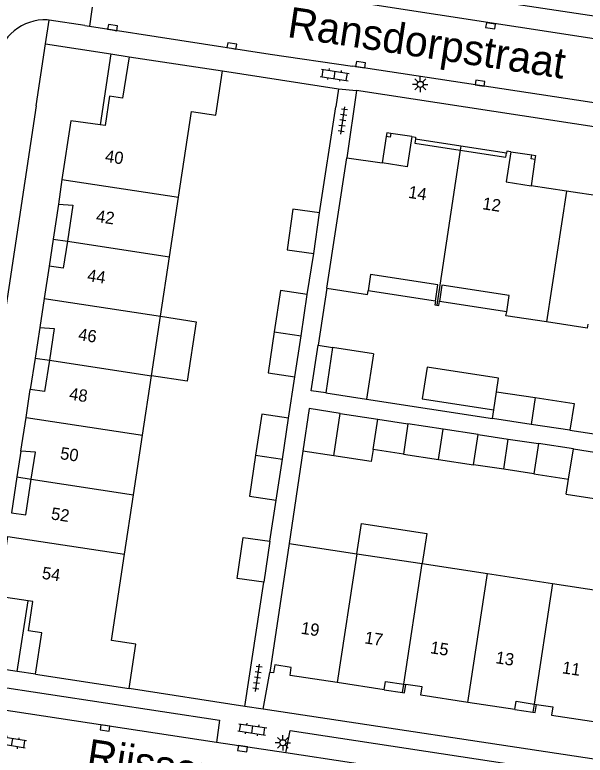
# Model space of a CAD drawing. Extents: x 124000 to 128010, y 398999 to 403000.
# Drawn here: x 126578 to 126624.6, y 399996.7 to 400057.2 of the extents above; entities that cross this region are included whole.
import ezdxf

# ---------------------------------------------------------------- set-up
doc = ezdxf.new("R2010")
doc.units = 0
for name, color, linetype in [('gg-afsc-erfafscheiding', 7, 'Continuous'), ('gg-afsc-hekwerk', 7, 'Continuous'), ('gg-afsc-muur', 7, 'Continuous'), ('gg-anno-huisnummerreeks BGT', 7, 'Continuous'), ('gg-anno-openbare ruimte label', 7, 'Continuous'), ('gg-bbg-bijgebouw', 7, 'Continuous'), ('gg-bbg-gedigitaliseerde bijgebouw', 7, 'Continuous'), ('gg-bbg-hoofdgebouw', 7, 'Continuous'), ('gg-bbg-luifel en loopbrug', 7, 'Continuous'), ('gg-bbg-onder overbouw', 7, 'Continuous'), ('gg-bbg-pand overbouw', 7, 'Continuous'), ('gg-bbg-pilaar onder overbouw', 7, 'Continuous'), ('gg-bbg-pilaar pand', 7, 'Continuous'), ('gg-bbg-tussenscheiding', 7, 'Continuous'), ('gg-bbg-tussenscheiding niveau 01', 7, 'Continuous'), ('gg-knt-verharding', 7, 'Continuous'), ('gg-knt-verharding nz', 7, 'Continuous'), ('gt-grn-weggrens', 7, 'Continuous'), ('gt-symb-klinker verharding', 7, 'Continuous'), ('gt-symb-kolk', 7, 'Continuous'), ('gt-symb-lichtmast', 7, 'Continuous'), ('gt-symb-tegel verharding', 7, 'Continuous')]:
    doc.layers.add(name, color=color, linetype=linetype)

# ---------------------------------------------------------------- blocks, each defined once
blk = doc.blocks.new('gt0-KOLK')
at = {"layer": 'gt-symb-kolk'}
blk.add_lwpolyline([(0, 0), (0.375, 0), (0.375, 0.4), (-0.375, 0.4), (-0.375, 0), (0, 0)], dxfattribs=at)
blk = doc.blocks.new('gt0-TEG1')
at = {"layer": 'gt-symb-tegel verharding'}
for p, q in [((-1.125, 0), (1.125, 0)), ((-0.9, -0.25), (-0.9, 0.25)), ((-0.45, -0.25), (-0.45, 0.25)), ((0, -0.25), (0, 0.25)), ((0.45, -0.25), (0.45, 0.25)), ((0.9, -0.25), (0.9, 0.25))]:
    blk.add_line(p, q, dxfattribs=at)
blk = doc.blocks.new('gt0-LMAST')
at = {"layer": 'gt-symb-lichtmast'}
for p, q in [((-0.005, 0.246), (-0.005, 0.621)), ((-0.182, 0.173), (-0.447, 0.438)), ((0.172, 0.173), (0.437, 0.438)), ((-0.255, -0.004), (-0.63, -0.004)), ((-0.182, -0.181), (-0.447, -0.446)), ((-0.005, -0.254), (-0.005, -0.629)), ((0.437, -0.446), (0.172, -0.181)), ((0.245, -0.004), (0.62, -0.004))]:
    blk.add_line(p, q, dxfattribs=at)
blk.add_circle((-0.005, -0.004), 0.25, dxfattribs=at)
blk = doc.blocks.new('gt0-KL1')
at = {"layer": 'gt-symb-klinker verharding'}
for p, q in [((-1.15, 0.3), (1.15, 0.3)), ((-1, -0.3), (-1, 0.3)), ((-0.5, 0.3), (-0.5, 0.45)), ((0, -0.3), (0, 0.3)), ((0.5, 0.3), (0.5, 0.45)), ((1, -0.3), (1, 0.3)), ((-1.15, -0.3), (1.15, -0.3)), ((-0.5, -0.45), (-0.5, -0.3)), ((0.5, -0.45), (0.5, -0.3))]:
    blk.add_line(p, q, dxfattribs=at)

msp = doc.modelspace()

# ---------------------------------------------------------------- linework, layer by layer
at = {"layer": 'gg-afsc-erfafscheiding'}
for p, q in [((126602.909, 400040.99), (126604.252, 400049.649)), ((126601.919, 400034.294), (126602.455, 400037.649)), ((126603.515, 400034.814), (126602.807, 400030.165)), ((126600.386, 400024.195), (126600.903, 400027.573)), ((126606.759, 400025.761), (126617.047, 400024.183)), ((126623.379, 400023.217), (126629.177, 400022.318)), ((126601.559, 400021.521), (126600.44, 400013.969)), ((126598.846, 400014.149), (126599.382, 400017.5))]:
    msp.add_line(p, q, dxfattribs=at)
at = {"layer": 'gg-afsc-hekwerk'}
msp.add_line((126596.82, 400000.66), (126598.377, 400010.794), dxfattribs=at)
at = {"layer": 'gg-afsc-muur'}
for p, q in [((126594.982, 400052.569), (126604.47, 400051.111)), ((126604.47, 400051.111), (126604.252, 400049.649)), ((126596.82, 400000.66), (126587.348, 400002.126))]:
    msp.add_line(p, q, dxfattribs=at)
at = {"layer": 'gg-bbg-bijgebouw'}
for p, q in [((126602.455, 400037.649), (126602.909, 400040.99)), ((126601.411, 400030.934), (126601.919, 400034.294)), ((126600.903, 400027.573), (126601.411, 400030.934)), ((126602.807, 400030.165), (126603.987, 400029.985)), ((126603.987, 400029.985), (126603.421, 400026.27)), ((126617.154, 400024.881), (126617.381, 400026.366)), ((126617.381, 400026.366), (126620.544, 400025.883)), ((126617.047, 400024.183), (126617.154, 400024.881)), ((126599.884, 400020.847), (126600.386, 400024.195)), ((126620.215, 400023.7), (126617.047, 400024.183)), ((126623.379, 400023.217), (126620.215, 400023.7)), ((126599.382, 400017.5), (126599.884, 400020.847)), ((126598.846, 400014.149), (126598.377, 400010.794))]:
    msp.add_line(p, q, dxfattribs=at)
for points in [[(126602.909, 400040.99), (126600.737, 400041.285), (126600.283, 400037.944), (126602.455, 400037.649)], [(126601.919, 400034.294), (126599.73, 400034.625), (126599.222, 400031.265)], [(126599.222, 400031.265), (126598.714, 400027.904), (126600.903, 400027.573)], [(126603.421, 400026.27), (126602.241, 400026.45), (126602.807, 400030.165)], [(126620.544, 400025.883), (126623.712, 400025.399), (126623.379, 400023.217)], [(126600.386, 400024.195), (126598.195, 400024.524), (126597.693, 400021.176)], [(126597.693, 400021.176), (126597.191, 400017.828), (126599.382, 400017.5)], [(126598.377, 400010.794), (126596.195, 400011.099), (126596.664, 400014.454), (126598.846, 400014.149)]]:
    msp.add_lwpolyline(points, dxfattribs=at)
at = {"layer": 'gg-bbg-gedigitaliseerde bijgebouw'}
for p, q in [((126604.087, 400021.137), (126604.612, 400024.588)), ((126604.612, 400024.588), (126607.669, 400024.122)), ((126607.669, 400024.122), (126610.142, 400023.746)), ((126610.142, 400023.746), (126609.766, 400021.276)), ((126615.499, 400020.404), (126615.874, 400022.875)), ((126615.874, 400022.875), (126618.344, 400022.5)), ((126618.344, 400022.5), (126620.816, 400022.124)), ((126609.766, 400021.276), (126607.297, 400021.651)), ((126620.816, 400022.124), (126620.44, 400019.653)), ((126623.269, 400019.223), (126623.661, 400021.691)), ((126623.661, 400021.691), (126629.076, 400020.868)), ((126617.971, 400020.028), (126615.499, 400020.404)), ((126620.44, 400019.653), (126617.971, 400020.028)), ((126623.073, 400017.986), (126623.269, 400019.223)), ((126623.073, 400017.986), (126628.488, 400017.165))]:
    msp.add_line(p, q, dxfattribs=at)
msp.add_lwpolyline([(126607.297, 400021.651), (126607.148, 400020.671), (126604.087, 400021.137)], dxfattribs=at)
at = {"layer": 'gg-bbg-hoofdgebouw'}
for p, q in [((126587.346, 400053.732), (126594.982, 400052.569)), ((126603.515, 400034.814), (126605.137, 400045.482)), ((126605.137, 400045.482), (126608.042, 400045.061)), ((126581.869, 400043.696), (126581.571, 400041.693)), ((126623.101, 400042.751), (126620.204, 400043.191)), ((126626.002, 400042.311), (126623.101, 400042.751)), ((126590.662, 400037.39), (126591.397, 400042.25)), ((126589.927, 400032.531), (126590.662, 400037.39)), ((126580.809, 400036.632), (126580.405, 400033.976)), ((126580.405, 400033.976), (126580.045, 400031.607)), ((126589.191, 400027.672), (126589.927, 400032.531)), ((126588.456, 400022.812), (126589.191, 400027.672)), ((126578.929, 400024.258), (126579.277, 400026.546)), ((126578.512, 400021.517), (126578.929, 400024.258)), ((126587.72, 400017.953), (126588.456, 400022.812)), ((126586.985, 400013.094), (126587.72, 400017.953)), ((126600.44, 400013.969), (126598.842, 400003.44)), ((126600.44, 400013.969), (126605.962, 400013.131)), ((126605.962, 400013.131), (126611.299, 400012.321)), ((126611.299, 400012.321), (126616.649, 400011.509)), ((126616.649, 400011.509), (126621.968, 400010.702)), ((126621.968, 400010.702), (126627.307, 400009.892)), ((126579.691, 400003.284), (126587.348, 400002.126)), ((126608.197, 400002.024), (126604.354, 400002.604)), ((126618.886, 400000.401), (126615.042, 400000.987))]:
    msp.add_line(p, q, dxfattribs=at)
for points in [[(126587.346, 400053.732), (126586.827, 400050.352), (126585.755, 400050.501), (126585.392, 400048.113), (126584.982, 400048.17)], [(126591.397, 400042.25), (126592.457, 400049.251), (126594.434, 400048.949), (126594.982, 400052.569)], [(126584.982, 400048.17), (126582.586, 400048.505), (126581.869, 400043.696)], [(126610.459, 400047.203), (126610.767, 400047.161), (126610.747, 400047.009)], [(126618.545, 400045.97), (126618.218, 400046.019), (126618.198, 400045.862)], [(126603.515, 400034.814), (126606.843, 400034.306), (126606.892, 400034.615)], [(126612.381, 400033.764), (126612.332, 400033.459), (126612.49, 400033.435)], [(126612.49, 400033.435), (126612.657, 400033.41), (126612.708, 400033.742)], [(126621.476, 400032.068), (126618.154, 400032.572), (126618.224, 400032.888)], [(126624.844, 400031.886), (126624.795, 400031.564), (126621.476, 400032.068)], [(126579.092, 400009.291), (126576.702, 400009.644), (126577.453, 400014.541)], [(126587.348, 400002.126), (126587.896, 400005.744), (126585.918, 400006.043), (126586.985, 400013.094)], [(126579.691, 400003.284), (126580.209, 400006.672), (126579.121, 400006.837), (126579.492, 400009.232), (126579.092, 400009.291)], [(126604.354, 400002.604), (126600.507, 400003.185), (126600.607, 400003.847), (126599.256, 400004.059), (126599.142, 400003.389), (126598.842, 400003.44)], [(126615.042, 400000.987), (126611.193, 400001.574), (126611.297, 400002.256), (126609.974, 400002.45)], [(126620.645, 400000.825), (126621.977, 400000.625), (126621.874, 399999.953), (126625.699, 399999.366)]]:
    msp.add_lwpolyline(points, dxfattribs=at)
at = {"layer": 'gg-bbg-luifel en loopbrug'}
for p, q in [((126585.864, 400053.962), (126584.982, 400048.17)), ((126585.864, 400053.962), (126587.346, 400053.732)), ((126607.328, 400029.471), (126603.987, 400029.985)), ((126607.328, 400029.471), (126606.759, 400025.761)), ((126603.421, 400026.27), (126606.759, 400025.761)), ((126613.008, 400023.311), (126610.142, 400023.746)), ((126612.633, 400020.84), (126613.008, 400023.311)), ((126615.874, 400022.875), (126613.008, 400023.311)), ((126623.661, 400021.691), (126620.816, 400022.124)), ((126604.087, 400021.137), (126601.559, 400021.521)), ((126609.766, 400021.276), (126612.633, 400020.84)), ((126612.633, 400020.84), (126615.499, 400020.404)), ((126620.44, 400019.653), (126623.269, 400019.223)), ((126578.208, 400003.509), (126579.092, 400009.291)), ((126579.691, 400003.284), (126578.208, 400003.509))]:
    msp.add_line(p, q, dxfattribs=at)
for points in [[(126589.927, 400032.531), (126592.843, 400032.086), (126592.101, 400027.228), (126589.191, 400027.672)], [(126617.381, 400026.366), (126617.553, 400027.485), (126611.715, 400028.38), (126611.315, 400025.776), (126617.154, 400024.881)], [(126604.612, 400024.588), (126602.072, 400024.981), (126601.559, 400021.521)], [(126605.962, 400013.131), (126606.337, 400015.603), (126611.674, 400014.793), (126611.299, 400012.321)]]:
    msp.add_lwpolyline(points, dxfattribs=at)
at = {"layer": 'gg-bbg-onder overbouw'}
for p, q in [((126609.795, 400002.476), (126609.974, 400002.45)), ((126620.463, 400000.852), (126620.645, 400000.825))]:
    msp.add_line(p, q, dxfattribs=at)
for points in [[(126610.459, 400047.203), (126610.065, 400044.74), (126608.042, 400045.061)], [(126610.747, 400047.009), (126610.703, 400046.672), (126614.416, 400046.102)], [(126614.416, 400046.102), (126618.154, 400045.528), (126618.198, 400045.862)], [(126618.545, 400045.97), (126618.169, 400043.5), (126620.204, 400043.191)], [(126581.571, 400041.693), (126582.756, 400041.617), (126582.309, 400038.658)], [(126582.309, 400038.658), (126581.976, 400036.455), (126580.809, 400036.632)], [(126612.381, 400033.764), (126612.597, 400035.099), (126607.093, 400035.947), (126606.892, 400034.615)], [(126618.224, 400032.888), (126618.425, 400034.214), (126612.91, 400035.056), (126612.708, 400033.742)], [(126580.045, 400031.607), (126581.23, 400031.517), (126580.837, 400028.94)], [(126580.837, 400028.94), (126580.444, 400026.369), (126579.277, 400026.546)], [(126579.36, 400019.222), (126579.697, 400021.437), (126578.512, 400021.517)], [(126577.749, 400016.475), (126578.915, 400016.296), (126579.36, 400019.222)], [(126608.197, 400002.024), (126608.299, 400002.696), (126609.795, 400002.476)], [(126618.886, 400000.401), (126618.988, 400001.073), (126620.463, 400000.852)]]:
    msp.add_lwpolyline(points, dxfattribs=at)
at = {"layer": 'gg-bbg-pand overbouw'}
for p, q in [((126608.374, 400047.208), (126608.042, 400045.061)), ((126610.459, 400047.203), (126608.744, 400047.468)), ((126614.467, 400046.436), (126610.747, 400047.009)), ((126618.198, 400045.862), (126614.467, 400046.436)), ((126618.545, 400045.97), (126620.257, 400045.711)), ((126620.523, 400045.345), (126620.204, 400043.191)), ((126581.571, 400041.693), (126581.141, 400038.835)), ((126581.141, 400038.835), (126580.809, 400036.632)), ((126612.381, 400033.764), (126606.892, 400034.615)), ((126618.224, 400032.888), (126612.708, 400033.742)), ((126580.045, 400031.607), (126579.667, 400029.118)), ((126579.667, 400029.118), (126579.277, 400026.546)), ((126578.512, 400021.517), (126578.191, 400019.399)), ((126578.191, 400019.399), (126577.749, 400016.475)), ((126608.197, 400002.024), (126609.691, 400001.792)), ((126618.886, 400000.401), (126620.36, 400000.178))]:
    msp.add_line(p, q, dxfattribs=at)
for points in [[(126609.691, 400001.792), (126609.868, 400001.765), (126609.974, 400002.45)], [(126620.36, 400000.178), (126620.543, 400000.15), (126620.645, 400000.825)]]:
    msp.add_lwpolyline(points, dxfattribs=at)
at = {"layer": 'gg-bbg-pilaar onder overbouw'}
for points in [[(126608.744, 400047.468), (126608.692, 400047.157), (126608.374, 400047.208)], [(126620.523, 400045.345), (126620.209, 400045.394), (126620.257, 400045.711)]]:
    msp.add_lwpolyline(points, dxfattribs=at)
at = {"layer": 'gg-bbg-pilaar pand'}
for points in [[(126608.744, 400047.468), (126608.425, 400047.522), (126608.374, 400047.208)], [(126620.257, 400045.711), (126620.572, 400045.663), (126620.523, 400045.345)]]:
    msp.add_lwpolyline(points, dxfattribs=at)
at = {"layer": 'gg-bbg-tussenscheiding'}
for p, q in [((126614.416, 400046.102), (126612.49, 400033.435)), ((126581.869, 400043.696), (126591.397, 400042.25)), ((126623.101, 400042.751), (126621.476, 400032.068)), ((126582.309, 400038.658), (126590.662, 400037.39)), ((126580.405, 400033.976), (126589.927, 400032.531)), ((126599.222, 400031.265), (126601.411, 400030.934)), ((126580.837, 400028.94), (126589.191, 400027.672)), ((126620.544, 400025.883), (126620.215, 400023.7)), ((126578.929, 400024.258), (126588.456, 400022.812)), ((126607.297, 400021.651), (126607.669, 400024.122)), ((126617.971, 400020.028), (126618.344, 400022.5)), ((126597.693, 400021.176), (126599.884, 400020.847)), ((126579.36, 400019.222), (126587.72, 400017.953)), ((126577.453, 400014.541), (126586.985, 400013.094)), ((126605.962, 400013.131), (126604.354, 400002.604)), ((126609.795, 400002.476), (126611.299, 400012.321)), ((126615.042, 400000.987), (126616.649, 400011.509)), ((126621.968, 400010.702), (126620.463, 400000.852))]:
    msp.add_line(p, q, dxfattribs=at)
at = {"layer": 'gg-bbg-tussenscheiding niveau 01'}
for p, q in [((126614.467, 400046.436), (126614.416, 400046.102)), ((126581.141, 400038.835), (126582.309, 400038.658)), ((126579.667, 400029.118), (126580.837, 400028.94)), ((126578.191, 400019.399), (126579.36, 400019.222)), ((126609.691, 400001.792), (126609.795, 400002.476)), ((126620.463, 400000.852), (126620.36, 400000.178))]:
    msp.add_line(p, q, dxfattribs=at)
at = {"layer": 'gg-knt-verharding'}
for p, q in [((126584.836, 400061.298), (126584.105, 400056.219)), ((126661.242, 400051.623), (126607.368, 400059.761)), ((126630.844, 400054.355), (126605.67, 400058.209)), ((126579.76, 400049.716), (126580.524, 400054.789)), ((126580.524, 400054.789), (126585.864, 400053.962)), ((126630.032, 400049.236), (126605.599, 400052.972)), ((126604.47, 400051.111), (126605.943, 400050.981)), ((126605.943, 400050.981), (126605.137, 400045.482)), ((126659.813, 400042.745), (126605.943, 400050.981)), ((126579.76, 400049.716), (126572.89, 400004.317)), ((126578.208, 400003.509), (126572.89, 400004.317)), ((126598.304, 400000.436), (126598.842, 400003.44)), ((126598.304, 400000.436), (126596.82, 400000.66)), ((126652.147, 399992.295), (126598.304, 400000.436)), ((126600.151, 399996.871), (126594.485, 399997.72))]:
    msp.add_line(p, q, dxfattribs=at)
for points in [[(126584.105, 400056.219), (126598.886, 400053.939), (126605.599, 400052.972)], [(126575.731, 400000.561), (126576.072, 400002.367), (126594.728, 399999.544), (126594.485, 399997.72)], [(126600.151, 399996.871), (126600.529, 399998.687), (126647.359, 399991.553), (126647.128, 399989.757)]]:
    msp.add_lwpolyline(points, dxfattribs=at)
at = {"layer": 'gg-knt-verharding nz'}
for p, q in [((126580.809, 400056.724), (126580.671, 400056.745)), ((126583.728, 400056.277), (126580.809, 400056.724)), ((126583.728, 400056.277), (126584.105, 400056.219)), ((126594.485, 399997.72), (126575.731, 400000.561)), ((126622.56, 399993.477), (126600.151, 399996.871))]:
    msp.add_line(p, q, dxfattribs=at)
msp.add_arc((126580.493, 400052.743), 4.006, 87.45911, 170.96405, dxfattribs=at)
at = {"layer": 'gt-grn-weggrens'}
msp.add_line((126580.524, 400054.789), (126580.809, 400056.724), dxfattribs=at)

# ---------------------------------------------------------------- block references
at = {"layer": 'gt-symb-klinker verharding'}
for p, rotation in [((126604.16, 400052.243), -8.567589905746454), ((126597.419, 399998.779), -8.510934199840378), ((126577.774, 399997.722), 170.62242087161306)]:
    msp.add_blockref('gt0-KL1', p, dxfattribs=dict(at, rotation=rotation))
at = {"layer": 'gt-symb-kolk'}
for p, rotation in [((126585.971, 400055.917), -9.556527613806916), ((126616.922, 400056.449), 171.25383773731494), ((126595.713, 400054.421), -9.556527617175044), ((126606.235, 400052.889), -8.680850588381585), ((126615.995, 400051.37), -8.746162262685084), ((126585.419, 399999.087), 171.43241009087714), ((126596.653, 399997.402), 171.3757712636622)]:
    msp.add_blockref('gt0-KOLK', p, dxfattribs=dict(at, rotation=rotation))
at = {"layer": 'gt-symb-lichtmast'}
for p in [(126611.153, 400051.474), (126599.923, 399997.689)]:
    msp.add_blockref('gt0-LMAST', p, dxfattribs=at)
at = {"layer": 'gt-symb-tegel verharding'}
for p, rotation in [((126604.82, 400048.529), 81.37577126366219), ((126597.843, 400002.998), 81.37577126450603)]:
    msp.add_blockref('gt0-TEG1', p, dxfattribs=dict(at, rotation=rotation))

# ---------------------------------------------------------------- texts
at = {"layer": 'gg-anno-huisnummerreeks BGT'}
for s, rotation, p in [('40', 351.5, (126585.344, 400045.148)), ('14', 351.3, (126610.124, 400042.208)), ('12', 351.3, (126616.179, 400041.279)), ('42', 351.5, (126584.609, 400040.241)), ('44', 351.4, (126583.884, 400035.41)), ('46', 351.4, (126583.15, 400030.584)), ('48', 351.4, (126582.413, 400025.727)), ('50', 351.4, (126581.674, 400020.868)), ('52', 351.3, (126580.926, 400015.941)), ('54', 351.3, (126580.184, 400011.092)), ('19', 351.4, (126601.354, 400006.597)), ('17', 351.4, (126606.547, 400005.813)), ('15', 351.3, (126611.915, 400005.006)), ('13', 351.3, (126617.262, 400004.19)), ('11', 351.3, (126622.693, 400003.369))]:
    msp.add_text(s, height=1, rotation=rotation, dxfattribs=at).set_placement(p)
at = {"layer": 'gg-anno-openbare ruimte label'}
for s, p in [('Ransdorpstraat', (126600.203, 400055.351)), ('Rijssenstraat', (126583.776, 399995.547))]:
    msp.add_text(s, height=2.5, rotation=351.4, dxfattribs=at).set_placement(p)

doc.saveas('drawing.dxf')
